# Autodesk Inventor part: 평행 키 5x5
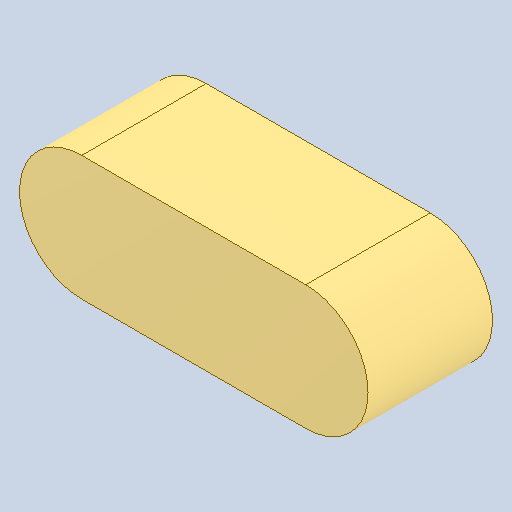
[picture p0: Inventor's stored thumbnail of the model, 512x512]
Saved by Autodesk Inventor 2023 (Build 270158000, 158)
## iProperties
Created: 2025-04
Part Number: 평행 키 5x5
Material: 강철, 연강
Document SubType Name: Modeling
Designer: Admin
Density: 7.86 g/cm^3
Appearance: 기본값
Author: jhkim
Revision Number: 1
Sending System: Autodesk Inventor 2026
Preprocessor: ST-DEVELOPER v20.1
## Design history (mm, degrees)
feature "솔리드1"
node "솔리드2"
